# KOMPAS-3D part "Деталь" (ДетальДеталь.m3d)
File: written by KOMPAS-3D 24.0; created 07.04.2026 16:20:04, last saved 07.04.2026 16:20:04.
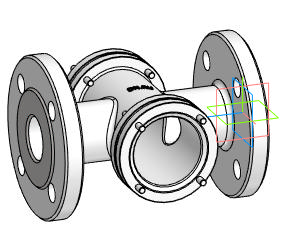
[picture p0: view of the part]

Document properties: Автор: Main; Полное имя файла: D:\DN.ru Аутсерс\Стекло смотровое DN.ru\Исходники\Стекло смотровое DN.ru SG2-34G-F тип В ГОСТ 21836-2021 Ду40 Ру40, углеродистая сталь, фланцевое\ДетальДеталь.m3d

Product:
- Body: Твердое тело1  | qty 1
- Part/product: Деталь
    additional columns: Типовые

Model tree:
1. Твердое тело1  (labels: Твердое тело1)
